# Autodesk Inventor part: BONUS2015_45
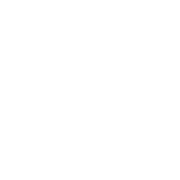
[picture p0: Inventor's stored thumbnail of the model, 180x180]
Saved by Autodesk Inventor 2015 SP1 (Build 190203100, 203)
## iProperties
Created: 2015-05
Part Number: BONUS2015_45
Material: Generisch
Document SubType Name: Modeling
Density: 1 g/cm^3
Appearance: Vorgabe
xx: 45
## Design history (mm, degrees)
